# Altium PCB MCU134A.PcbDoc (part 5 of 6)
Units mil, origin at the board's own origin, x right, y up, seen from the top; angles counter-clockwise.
Board outline 4163.98 x 2693.8 mil, 6 copper layers (Top Layer, GND1, SIG1, PWR, GND2, Bottom), stack 58.132 mil thick; 218 components, 287 nets, 1260 pads, 770 vias.
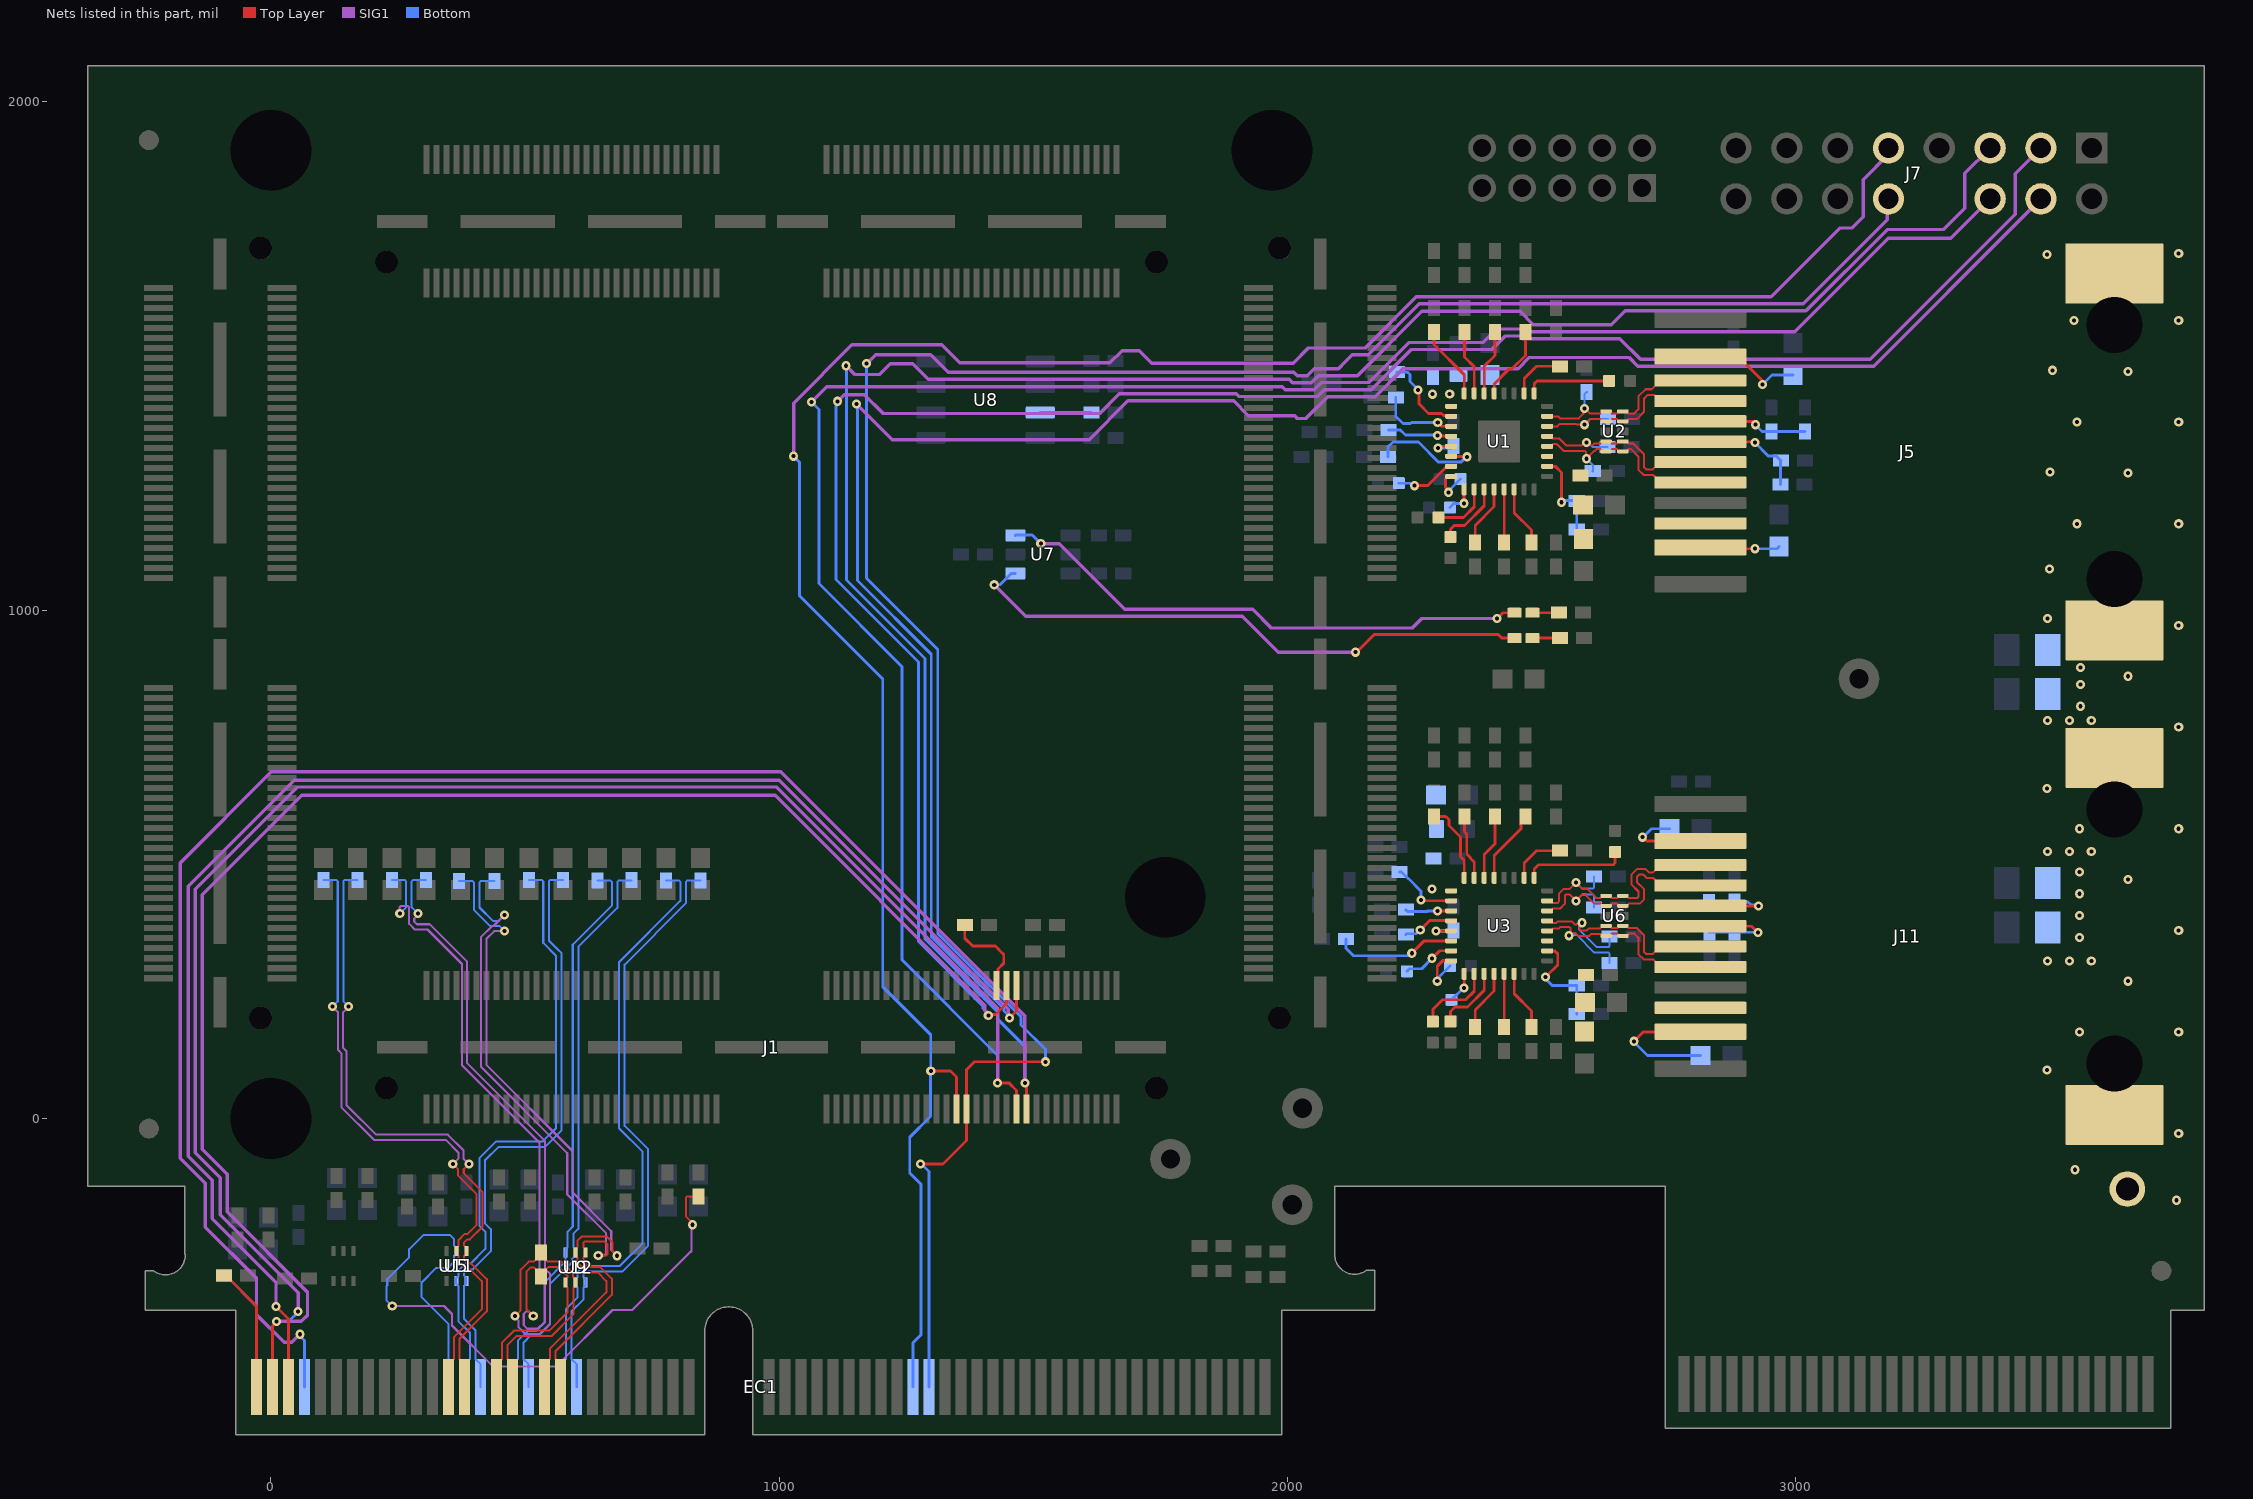
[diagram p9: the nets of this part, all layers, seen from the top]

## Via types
v1: diameter 18, hole 8, Top Layer to Bottom, tented both sides, 761 vias
v2: diameter 19.68, hole 7.87, Top Layer to Bottom, tented both sides, 9 vias

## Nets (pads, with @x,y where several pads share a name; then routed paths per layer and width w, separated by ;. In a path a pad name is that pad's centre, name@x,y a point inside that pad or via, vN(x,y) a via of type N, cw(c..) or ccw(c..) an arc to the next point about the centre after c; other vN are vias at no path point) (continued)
HSEC_PIN25: EC1.25 R103.1 U5.5 | length 1310
  Top Layer w4: EC1.25@349.86,-528.32 349.86,-484.03 360.11,-473.78 360.11,-430.36 415,-375.47 415,-320.36 390.24,-295.6 382.58,-295.6 369.34,-282.36 369.34,-270.66 367,-268.31 366.94,-268.31 365,-266.38 U5.5@365,-260.47 365,-254.57 366.94,-252.63 367,-252.63 369.34,-250.29 369.34,-239.31 381.65,-227 387.04,-227 405,-209.04 405,-148.98 368.5,-112.48 368.5,-99.9 358.6,-90 v1(358,-90)
  SIG1 w4.2: v1(121.07,220) 131.97,209.1 131.97,134.78 138.75,128 138.75,21.83 202.78,-42.2 344.1,-42.2 368.9,-67 368.9,-79.1 v1(358,-90)
  Bottom w4: R103.1@103.59,468.94 129.23,468.94 131.57,466.59 131.57,230.5 v1(121.07,220)
HSEC_PIN26: EC1.26 R114.1 U11.2 | length 1478.6
  Top Layer w4: v1(829.79,-209.28) 829.79,-206.24 816.38,-192.83 816.38,-156.25 818.72,-153.91 R114.1@841.45,-153.91
  SIG1 w4.2: v1(238.77,-369.17) 238.84,-369.1 340.8,-369.1 356.43,-384.73 356.43,-407.43 437.46,-488.46 560.77,-488.46 672.22,-377 711.23,-377 803.91,-284.32 804.02,-284.32 821.57,-266.76 ; 821.59,-266.76 827.6,-260.75 827.6,-211.46 v1(829.79,-209.28)
  Bottom w4: v1(238.77,-369.17) 227.19,-357.59 227.19,-330.59 229,-328.78 229,-316.44 272,-273.44 272,-257.44 300.44,-229 351.87,-229 360.66,-237.79 360.66,-250.29 363,-252.63 363.06,-252.63 365,-254.57 U11.2@365,-260.47 ; EC1.26@349.86,-528.32 349.86,-404.86 296.5,-351.5 296.5,-322.84 325.22,-294.12 348.61,-294.12 360.34,-282.39 360.34,-270.66 362.69,-268.31 362.75,-268.31 364.69,-266.38 U11.2@364.69,-260.47
HSEC_PIN27: EC1.27 R104.1 U5.4 | length 1308.3
  Top Layer w4: EC1.27@381.36,-528.32 381.36,-484.03 371.11,-473.78 371.11,-433.5 425,-379.62 425,-316.21 393.39,-284.6 387.14,-284.6 380.34,-277.8 380.34,-270.66 382.69,-268.31 382.75,-268.31 384.69,-266.38 U5.4@384.69,-260.47 384.69,-254.57 382.75,-252.63 382.69,-252.63 380.34,-250.29 380.34,-243.87 386.21,-238 391.6,-238 416,-213.6 416,-144.42 379.5,-107.92 379.5,-99.9 389.4,-90 v1(390,-90)
  SIG1 w4.2: v1(153.07,220) 142.17,209.1 142.17,139 145.96,135.21 148.95,132.22 148.95,26.05 207,-32 348.32,-32 379.1,-62.78 379.1,-79.1 v1(390,-90)
  Bottom w4: v1(153.07,220) 142.57,230.5 142.57,466.59 144.92,468.94 R104.1@170.55,468.94
HSEC_PIN28: EC1.28 R115.1 U11.5 | length 1201
  Bottom w4: EC1.28@381.36,-528.32 381.36,-484.03 391.61,-473.78 391.61,-421.61 388.39,-418.39 369.03,-399.03 369.03,-348.28 369.03,-329.71 366.68,-327.37 366.62,-327.37 364.69,-325.43 364.69,-313.62 366.62,-311.69 367,-311.69 369.34,-309.34 369.34,-298.84 382.33,-285.86 392.72,-285.86 422,-256.57 422,-222.65 410.15,-210.8 410.15,-78.29 443.44,-45 535,-45 561,-19 561,320.44 535.92,345.53 535.92,466.59 533.57,468.94 R115.1@507.7,468.94
HSEC_PIN30: EC1.30 R116.1 U11.4 | length 1200.6
  Bottom w4: EC1.30@412.86,-528.32 412.86,-484.03 402.61,-473.78 402.61,-417.05 399.39,-413.83 380.03,-394.47 380.03,-343.73 380.03,-329.71 382.37,-327.37 382.43,-327.37 384.37,-325.43 384.37,-313.31 382.75,-311.69 382.69,-311.69 380.34,-309.34 380.34,-303.4 386.88,-296.86 397.27,-296.86 433,-261.13 433,-218.1 421.15,-206.25 421.15,-82.85 448,-56 539.56,-56 572,-23.56 572,325 564,333 546.92,350.08 546.92,466.59 549.26,468.94 R116.1@575.14,468.94
HSEC_PIN31: C25.1 EC1.31 R105.1 U9.1 | length 1689
  Top Layer w4: EC1.31@444.35,-528.32 444.35,-484.03 454.41,-473.98 454.41,-441.45 478.41,-417.45 547.55,-417.45 584.01,-380.99 584.01,-332.85 581.66,-330.5 581.6,-330.5 579.66,-328.57 579.66,-316.76 583.52,-312.9 583.52,-309.16 566.9,-292.55 546,-292.55 C25.1@541.22,-297.33 ; v1(516.29,-388.69) 502.63,-375.02 502.63,-302.07 511.73,-292.97 517.22,-292.97 C25.1@531.41,-307.16 ; C25.1@531.41,-311.09 C25.1@531.41,-307.14 ; C25.1@541.22,-297.34 C25.1@531.42,-307.14
  SIG1 w4.2: v1(253.65,403) 253,403.65 253,415 256.14,418.14 268.73,418.14 271.97,414.9 271.97,382.98 283.15,371.8 308.1,371.8 376,303.9 376,104.49 528.89,-48.4 528.89,-299.77 538.9,-309.78 538.9,-399.87 524.77,-414 504.79,-414 497.62,-406.83 497.62,-384.8 502.64,-379.78 507.04,-379.78 515.94,-388.69 v1(516.29,-388.69)
  Bottom w4: R105.1@237.93,468.94 263.81,468.94 266.15,466.59 266.15,415.5 v1(253.65,403)
HSEC_PIN33: C25.2 EC1.33 R106.1 U9.2 | length 1690.6
  Top Layer w4: EC1.33@475.85,-528.32 475.85,-484.03 465.41,-473.59 465.41,-467.75 465.41,-446 482.96,-428.45 552.1,-428.45 595.01,-385.55 595.01,-332.85 597.35,-330.5 597.41,-330.5 599.35,-328.57 599.35,-316.76 594.52,-311.92 594.52,-304.61 571.46,-281.55 545.01,-281.55 541.22,-277.75 541.22,-277.6 531.57,-267.94 531.41,-267.94 C25.2@531.41,-263.85 ; v1(480.29,-388.69) 491.63,-377.35 491.63,-297.52 507.18,-281.97 517.22,-281.97 C25.2@531.41,-267.79
  SIG1 w4.2: v1(289.65,403) 289.65,400.54 282.17,393.06 282.17,387.2 287.38,382 312.32,382 386.2,308.12 386.2,108.72 539.09,-44.17 539.09,-295.55 549.1,-305.56 549.1,-404.1 529,-424.2 500.56,-424.2 487.42,-411.06 487.42,-398.05 480.29,-390.92 v1(480.29,-388.69)
  Bottom w4: v1(289.65,403) 277.15,415.5 277.15,466.59 279.49,468.94 R106.1@305.37,468.94
HSEC_PIN34: EC1.34 R117.1 U12.1 | length 1113.5
  Bottom w4: EC1.34@475.85,-528.32 475.85,-484.03 486.1,-473.78 486.1,-437.9 507,-417 523.51,-417 539,-401.51 539,-322 579.66,-281.34 579.66,-269.51 U12.1@579.66,-263.61 579.66,-257.7 U12.1@581.6,-255.76 ; U12.1@581.66,-255.76 584.01,-253.42 584.01,-222.65 594,-212.66 594,342 670.8,418.8 670.8,465.61 668.46,467.95 R117.1@642.58,467.95
HSEC_PIN36: EC1.36 R118.1 U12.2 | length 1117.1
  Bottom w4: EC1.36@507.34,-528.32 507.34,-484.03 497.1,-473.78 497.1,-441.05 511.14,-427 527.66,-427 549,-405.66 549,-326.14 592.6,-282.54 592.6,-276.26 599.35,-269.51 U12.2@599.35,-263.61 599.35,-257.7 U12.2@597.41,-255.76 ; U12.2@597.35,-255.76 595.01,-253.42 595.01,-227.21 605,-217.21 605,337.44 681.8,414.24 681.8,465.61 684.14,467.95 R118.1@710.02,467.95
HSEC_PIN37: EC1.37 R107.1 U9.5 | length 1417.9
  Top Layer w4: EC1.37@538.84,-528.32 538.84,-484.03 549.09,-473.78 549.09,-453.35 660,-342.44 660,-320.05 642.95,-303 623,-303 603.69,-283.69 603.69,-273.79 601.35,-271.45 601.29,-271.45 599.35,-269.51 U9.5@599.35,-263.61 599.35,-257.7 601.29,-255.76 601.35,-255.76 603.69,-253.42 603.69,-240.1 611.48,-232.31 660.76,-232.31 672,-243.55 672,-261.04 680.75,-269.79 v1(680.75,-270.19)
  SIG1 w4.2: v1(460,368.5) 439.5,368.5 424,353 424,105.42 593.49,-64.06 593.49,-145.55 669.79,-221.86 669.79,-258.83 v1@680.75,-269.79 ; v1(680.75,-270.19) v1@680.75,-269.79 ; v1@680.85,-269.89 v1@680.75,-269.79
  Bottom w4: R107.1@370,466.69 397.16,466.69 399.5,464.35 399.5,410.44 431.71,378.24 450.26,378.24 v1(460,368.5)
HSEC_PIN39: EC1.39 R108.1 U9.4 | length 1413.8
  Top Layer w4: EC1.39@570.34,-528.32 570.34,-484.03 560.09,-473.78 560.09,-457.91 671,-347 671,-315.5 648.32,-292.82 626.96,-292.82 614.69,-280.55 614.69,-273.79 617.03,-271.45 617.1,-271.45 619.03,-269.51 U9.4@619.03,-263.61 619.03,-257.7 617.1,-255.76 617.03,-255.76 614.69,-253.42 614.69,-244.65 617.03,-242.31 656.62,-242.31 661.9,-247.59 661.9,-267.42 659.32,-270 v1(644.19,-270)
  SIG1 w4.2: v1(460,400.5) 438.2,378.7 435.28,378.7 413.8,357.22 413.8,101.2 583.29,-68.29 583.29,-149.78 659.59,-226.08 659.59,-265.62 655.21,-270 v1(644.19,-270)
  Bottom w4: R108.1@440,466.69 412.84,466.69 410.5,464.35 410.5,415 437.26,388.24 447.16,388.24 459.42,400.5 v1(460,400.5)
HSEC_PIN40: EC1.40 R119.1 U12.5 | length 1204.3
  Bottom w4: EC1.40@570.34,-528.32 570.34,-484.03 580.59,-473.78 580.59,-375.27 603.69,-352.16 603.69,-332.85 601.35,-330.5 601.29,-330.5 599.35,-328.57 U12.5@599.35,-322.66 599.35,-316.76 601.29,-314.82 601.35,-314.82 603.69,-312.48 603.69,-302.26 615.47,-290.49 686.57,-290.49 731.36,-245.7 731.36,-65.36 685,-19 685,307.32 805.68,428 805.68,465.61 803.34,467.95 R119.1@777.46,467.95
HSEC_PIN42: EC1.42 R120.1 U12.4 | length 1204.3
  Bottom w4: EC1.42@601.83,-528.32 601.83,-484.03 591.59,-473.78 591.59,-379.82 614.69,-356.72 614.69,-332.85 617.03,-330.5 617.1,-330.5 619.03,-328.57 U12.4@619.03,-322.66 619.03,-316.76 617.1,-314.82 617.03,-314.82 614.69,-312.48 614.69,-306.82 620.02,-301.49 691.13,-301.49 742.36,-250.26 742.36,-60.8 696,-14.44 696,302.76 816.68,423.44 816.68,465.61 819.03,467.95 R120.1@844.9,467.95
MCU_SCI_RX: EC1.76 J1.33 J7.9 | length 4660.7
  Top Layer w5.66: v1(1298.5,93.41) 1337.51,93.41 1349.17,81.75 J1.33@1349.17,18.5
  SIG1 w6.66: v1(1028.49,1303) 1028.49,1407.18 1143.37,1522.06 1320.39,1522.06 1355.79,1486.66 1650.9,1486.66 1674.91,1510.66 1708.59,1510.66 1733.03,1486.22 2011.54,1486.22 2041.24,1515.93 2153.24,1515.93 2254,1616.68 2951.85,1616.68 3087.17,1752 3111,1752 3133,1774 3133,1847 3182.94,1896.94 J7.9@3182.94,1909.38
  Bottom w5.66: v1(1028.49,1303) 1040.24,1291.25 1040.24,1028.42 1204,864.66 1204,259 1298.5,164.5 v1(1298.5,93.41) 1298.02,92.92 1298.02,3.64 1257.17,-37.21 1257.17,-107.17 1279.5,-129.5 1279.5,-425.71 1263.66,-441.56 EC1.76@1263.66,-527.92
MCU_SCI_TX: EC1.78 J1.31 J7.10 | length 4579.4
  Top Layer w5.66: v1(1278,-90) 1322.31,-90 1368.86,-43.45 J1.31@1368.86,18.5 1368.86,95.91 1384.36,111.41 v1(1523.99,111.4)
  SIG1 w6.66: v1(1172,1485.18) 1189.82,1503 1298,1503 1333,1468.01 2012.99,1468.01 2019.57,1461.43 2039.09,1461.43 2052.98,1475.32 2100.74,1475.32 2114.24,1488.81 2114.24,1489.16 2127.34,1502.27 2158.9,1502.27 2259.66,1603.02 3014.97,1603.02 3180.43,1768.48 3180.43,1806.87 J7.10@3182.94,1809.38
  Bottom w5.66: v1(1172,1485.18) 1172,1063 1312.17,922.83 1312.17,363.69 1475.95,199.91 1475.95,184.05 1523.99,136.01 v1(1523.99,111.4) ; v1(1278,-90) 1280,-90 1294.75,-104.75 EC1.78@1294.75,-528.32
MCU_TCK: EC1.5 J1.22 J7.4 | length 6974.8
  Top Layer w5.66: v1(10,-370) 34.9,-394.9 EC1.5@34.9,-528.32 ; v1(1453.36,197.28) 1453.36,197.49 1467.28,211.41 J1.22@1467.28,261.5
  SIG1 w6.66: v1(10,-370) 10,-322 -115,-197 -115,-121.74 -162.32,-74.42 -162.32,457 46.34,665.66 1000.7,665.66 1451.19,215.17 1451.19,199.45 v1(1453.36,197.28) ; v1(1152,1405.83) 1222.26,1335.57 1610.18,1335.57 1686.47,1411.86 1894.31,1411.86 1923.56,1382.6 2014.31,1382.6 2019.76,1377.16 2036.31,1377.16 2079.5,1420.36 2173,1420.36 2227.64,1475 2454,1475 2476.33,1497.33 2672.35,1497.33 2689.34,1480.34 3153.9,1480.34 3445.66,1772.1 J7.4@3482.94,1809.38
  Bottom w5.66: v1(1152,1405.83) 1154,1403.83 1154,1058.7 1299.51,913.19 1299.51,358.45 1442.83,215.13 1442.83,211.16 1453.36,200.62 v1(1453.36,197.28)
MCU_TDI: EC1.8 J1.19 J7.5 | length 7385.2
  Top Layer w5.66: v1(1483.55,69.77) 1483.55,66.43 1486.97,63.02 J1.19@1486.97,18.5
  SIG1 w6.66: v1(57.25,-424.73) 41.25,-440.73 26.43,-440.73 -28.33,-385.97 -28.33,-314.67 -129.26,-213.74 -129.26,-127.92 -178.34,-78.84 -178.34,502.58 1.08,682 1003.68,682 1483.55,202.13 v1(1483.55,69.77) ; v1(1132,1481) 1149.33,1463.67 1197.36,1463.67 1218.69,1485 1263,1485 1293.65,1454.35 2003.65,1454.35 2010.23,1447.77 2047.46,1447.77 2061.35,1461.66 2137.61,1461.66 2137.8,1461.84 2138.77,1461.84 2264.92,1588 2458,1588 2484.26,1561.74 2637.37,1561.74 2665,1589.36 3020.63,1589.36 3180.27,1749 3290.97,1749 3333,1791.03 3333,1859.44 J7.5@3382.94,1909.38
  Bottom w5.66: v1(57.25,-424.73) 57.25,-428.07 66.4,-437.22 EC1.8@66.4,-528.32 ; v1(1132,1481) 1132.83,1480.17 1132.83,1059.18 1286.85,905.16 1286.85,353.2 1430.17,209.88 1430.17,195.26 1483.55,141.88 v1(1483.55,69.77)
MCU_TDO: EC1.6 J1.21 J7.6 | length 7125.2
  Top Layer w5.66: v1(1430,70) 1451.89,70 1467.28,54.61 J1.21@1467.28,18.5
  SIG1 w6.66: v1(53.21,-379.96) 54,-379.17 54,-343.08 -99.73,-189.35 -99.73,-116.56 -148.66,-67.63 -148.66,451.34 52,652 995.05,652 1430,217.05 v1(1430,70) ; v1(1064,1410) 1093.71,1439.71 1990.29,1439.71 1995.89,1434.11 2053.12,1434.11 2067.01,1448 2160,1448 2238.66,1526.66 2384.66,1526.66 2411.27,1553.27 2468.73,1553.27 2473.92,1548.08 2998.66,1548.08 3182.59,1732 3305.56,1732 J7.6@3382.94,1809.38
  Bottom w5.66: EC1.6@34.9,-528.32 34.9,-399.65 53.21,-381.35 v1(53.21,-379.96) ; v1(1064,1410) 1064,1409.23 1078.22,1395 1078.22,1052.4 1242.16,888.46 1242.16,311.65 1430,123.81 v1(1430,70)
MCU_TMS: EC1.3 J1.24 J7.3 | length 7034.6
  Top Layer w5.66: EC1.3@3.41,-528.32 3.41,-408.29 10.92,-400.78 v1(10.92,-399.29) ; v1(1411.67,202.5) 1413.54,204.37 1425.85,204.37 1447.6,226.12 J1.24@1447.6,261.5
  SIG1 w6.66: v1(10.92,-399.29) 59.8,-399.29 72.03,-387.06 72.03,-341.79 -86.07,-183.69 -86.07,-110.07 -135,-61.14 -135,440 60.58,635.58 992.15,635.58 1404.91,222.82 1404.91,212.33 1411.67,205.57 v1(1411.67,202.5) ; v1(1115,1411) 1128.16,1424.16 1167.39,1424.16 1204.54,1387 1630.59,1387 1669.11,1425.52 1899.96,1425.52 1905.04,1420.45 2058.78,1420.45 2072.35,1434.02 2165.34,1434.02 2244.32,1513 2402.69,1513 2429.31,1539.61 2458.39,1539.61 2463.58,1534.42 2654.58,1534.42 2695,1494 3146.71,1494 3432,1779.29 3432,1858.44 J7.3@3482.94,1909.38
  Bottom w5.66: v1(1115,1411) 1112.64,1408.64 1112.64,1402.15 1112,1401.51 1112,1060.5 1274.19,898.31 1274.19,347.96 1401.54,220.61 1401.54,215.97 1411.67,205.84 v1(1411.67,202.5)
NetC1_1: C1.1 C2.1 J5.5 | length 214.4
  Top Layer w5.66: J5.5@2812.8,1371.66 2914.34,1371.66 v1(2921,1365)
  Bottom w5.66: v1(2921,1365) 2934.24,1351.76 C2.1@2953,1351.76 C1.1@3019,1351.76
NetC3_1: C3.1 C8.1 U1.2 | length 179.6
  Top Layer w5.66: U1.2@2511.45,1283.11 2527.15,1283.11 2539.46,1270.79 v1(2539.49,1212.41)
  Bottom w5.66: v1(2539.49,1212.41) 2542.2,1212.41 2545.41,1215.62 2569.09,1215.62 C3.1@2569.54,1215.17 C8.1@2569.54,1158.65
NetC9_1: C9.1 C10.1 J5.6 | length 221.3
  Top Layer w5.66: J5.6@2812.8,1331.51 2918.49,1331.51 v1(2920,1330)
  Bottom w5.66: v1(2920,1330) 2946.39,1303.61 2962.09,1303.61 C9.1@2971.08,1294.63 2970.66,1294.21 C10.1@2970.66,1247
NetC11_1: C11.1 C13.1 R22.2 U1.3
NetC12_1: C12.1 C14.2 R21.1 U1.17
  other v1: 2286,1425 2319.54,1425.07
NetC15_1: C15.1 C16.1 R55.2 U3.3
NetC17_2: C17.2 C18.1 R54.1 U3.17
  other v1: 2284.99,451.67
NetC41_1: C41.1 C42.1 J11.5 | length 215.3
  Top Layer w5.66: J11.5@2812.8,418.38 2813.19,418 v1(2927,418)
  Bottom w5.66: C42.1@2829.4,426.1 2880,426.1 2906.68,426.1 2912.42,420.36 2924.64,420.36 v1(2927,418)
NetC47_1: C47.1 C48.1 U3.2 | length 205.8
  Top Layer w5.66: v1(2508,278) 2532.09,302.09 2532.09,323.95 2526.96,329.07 2512.2,329.07 U3.2@2511.45,329.83
  Bottom w5.66: v1(2508,278) 2508,274.66 2516.62,266.04 2516.62,265.89 2520.62,261.89 C48.1@2569.54,261.89 C47.1@2569.54,205.37
NetC49_1: C49.1 C50.1 J11.6 | length 214
  Top Layer w5.66: J11.6@2812.8,378.23 2913.49,378.23 2925.72,366 v1(2926,366)
  Bottom w5.66: C50.1@2830.36,366.22 C49.1@2880.36,366.22 2925.78,366.22 v1(2926,366)
NetD1_1: D1.1 R90.2 | length 51.8
  Top Layer w5.66: D1.1@2482.43,995 R90.2@2534.25,995
NetD1_2: D1.2 U7.6 | length 1070.8
  Top Layer w5.66: v1(2412.76,983.68) 2413.41,983.68 2424.73,995 D1.2@2447,995
  SIG1 w6.66: v1(1515,1130.96) 1551.04,1130.96 1680.32,1001.68 1931.66,1001.68 1968.34,965 2246,965 2264.68,983.68 v1(2412.76,983.68)
  Bottom w5.66: U7.6@1464.8,1147.21 1465.59,1148 1497.96,1148 v1(1515,1130.96)
NetD2_1: D2.1 R93.2 | length 53.8
  Top Layer w5.66: D2.1@2482.43,945 R93.2@2536.21,945
NetD2_2: D2.2 U7.4 | length 1146.4
  Top Layer w5.66: v1(2134,917.39) 2136.39,917.39 2171,952 2415,952 2422,945 D2.2@2447,945
  SIG1 w6.66: v1(1423.4,1050) 1485.38,988.02 1911.65,988.02 1982.28,917.39 v1(2134,917.39)
  Bottom w5.66: v1(1423.4,1050) 1434.52,1050 1456.93,1072.4 U7.4@1464.8,1072.4
NetEC1_1: EC1.1 R45.1 | length 247.8
  Top Layer w5.66: R45.1@-92.24,-309.39 -88.31,-309.39 -28.09,-369.61 EC1.1@-28.09,-528.32
NetEC1_2: EC1.2 R46.1 | length 247.8
  Bottom w5.66: R46.1@-92.24,-309.39 -88.31,-309.39 -28.09,-369.61 EC1.2@-28.09,-528.32
NetJ1_26: J1.26 R36.1 | length 183.4
  Top Layer w5.66: R36.1@1365.38,381 1365.38,354.62 1381,339 1426,339 1433,332 1433,331.52 1441.94,322.58 1441.94,305.36 1430.61,294.03 1430.61,264.2 J1.26@1427.91,261.5
NetJ5_2: J5.2 R38.2 | length 217.4
  Top Layer w5.66: J5.2@2812.8,1499.22 2887.41,1499.22 2935,1451.63 v1(2935,1444)
  Bottom w5.66: v1(2935,1444) 2954.01,1463.01 R38.2@2995,1463.01
NetJ5_11: J5.11 R25.2 | length 157.7
  Top Layer w5.66: J5.11@2812.8,1123.63 2815.44,1121 v1(2920,1121)
  Bottom w5.66: v1(2920,1121) 2963.76,1121 R25.2@2967.76,1125
NetJ11_2: J11.2 R87.2 | length 176.7
  Top Layer w5.66: v1(2698.99,553.33) 2699.93,553.33 2707.32,545.94 J11.2@2812.8,545.94
  Bottom w5.66: v1(2698.99,553.33) 2700.03,553.33 2716.72,570.02 R87.2@2751.93,570.02
NetJ11_11: J11.11 R79.2 | length 282.4
  Top Layer w5.66: v1(2682.02,151.75) 2700.63,170.35 J11.11@2812.8,170.35
  Bottom w5.66: v1(2682.02,151.75) 2682.02,150.05 2708.6,123.47 R79.2@2813.21,123.47
NetR2_2: R2.2 U1.21 | length 59.8
  Top Layer w5.66: v1(2296.37,1319.06) 2299.71,1319.06 2303.13,1322.48 U1.21@2322.47,1322.48
  Bottom w5.66: v1(2296.37,1319.06) 2322.96,1319.06 R2.2@2326.96,1323.05
NetR4_2: R4.2 U1.10 | length 109.4
  Top Layer w5.66: U1.10@2466.17,1426.81 2466.17,1456.14 2490.03,1480 R4.2@2536.38,1480
NetR5_1: R5.1 U1.23 | length 120.8
  Top Layer w5.66: v1(2250,1245) 2275.79,1245 2311.8,1281.02 2320.38,1281.02 U1.23@2322.47,1283.11
  Bottom w5.66: R5.1@2219.45,1249.88 2241.78,1249.88 2246.66,1245 v1(2250,1245)
NetR9_2: R9.2 U1.19 | length 156
  Top Layer w5.66: v1(2296.05,1369.05) 2296.63,1369.05 2303.83,1361.85 U1.19@2322.47,1361.85
  Bottom w5.66: R9.2@2213.41,1418.51 2213.41,1381.38 2227.61,1367.17 2242.39,1367.17 2244.42,1369.2 2295.9,1369.2 v1(2296.05,1369.05)
NetR10_1: R10.1 U1.27 | length 133.5
  Top Layer w5.66: R10.1@2320.94,1143.74 2320.94,1159.11 2328.52,1166.69 2348.77,1166.69 2387.43,1205.35 U1.27@2387.43,1237.83
NetR11_1: R11.1 U1.26 | length 112.9
  Top Layer w5.66: R11.1@2297.83,1182.57 2346.75,1182.57 2367.75,1203.57 U1.26@2367.75,1237.83
NetR12_1: R12.1 U1.25 | length 58.8
  Top Layer w5.66: v1(2347.78,1210.31) 2347.92,1210.45 2347.92,1237.69 U1.25@2348.06,1237.83
  Bottom w5.66: R12.1@2320.02,1202.13 2327.6,1209.71 2347.18,1209.71 v1(2347.78,1210.31)
NetR13_2: R13.2 U1.18 | length 166.3
  Top Layer w5.66: v1(2257.13,1433.03) 2259.49,1430.67 2259.49,1405.51 2277.75,1387.25 2303.43,1387.25 2307.68,1383.01 2321,1383.01 U1.18@2322.47,1381.53
  Bottom w5.66: R13.2@2215.47,1468.23 2236.77,1468.23 2241.16,1463.84 2241.16,1450.01 2257.13,1434.04 v1(2257.13,1433.03)
NetR14_1: R14.1 U1.24 | length 78.3
  Top Layer w5.66: v1(2317.12,1231.99) 2317.12,1235.23 2311.24,1241.12 2311.24,1259.08 2315.58,1263.42 U1.24@2322.47,1263.42
  Bottom w5.66: v1(2317.12,1231.99) 2317.12,1234.35 R14.1@2340.75,1257.97
NetR15_2: R15.2 U1.15 | length 128.8
  Top Layer w5.66: R15.2@2348.47,1547.63 2348.47,1498.48 2367.75,1479.2 U1.15@2367.75,1426.81
NetR16_2: R16.2 U1.14 | length 129.5
  Top Layer w5.66: U1.14@2387.43,1426.81 2387.43,1480.28 2408.47,1501.32 R16.2@2408.47,1547.63
NetR17_2: R17.2 U1.13 | length 149.3
  Top Layer w5.66: U1.13@2407.12,1426.81 2407.12,1445.29 2436.83,1475 2442.2,1475 2468.6,1501.4 R17.2@2468.6,1547.5
NetR18_2: R18.2 U1.20 | length 128.6
  Top Layer w5.66: v1(2295.83,1344.05) 2296.78,1343.11 2321.53,1343.11 U1.20@2322.47,1342.16
  Bottom w5.66: R18.2@2199.03,1354.64 2222.24,1354.64 2232.46,1344.42 2295.46,1344.42 v1(2295.83,1344.05)
NetR19_1: R19.1 U1.30 | length 118.7
  Top Layer w5.66: U1.30@2446.49,1237.83 2446.49,1191.54 2480.52,1157.51 R19.1@2480.52,1133.25
NetR20_2: R20.2 U1.22 | length 232.4
  Top Layer w5.66: U1.22@2322.14,1302.07 2322.36,1302.29 2353.43,1302.29 v1(2353.93,1301.79)
  Bottom w5.66: R20.2@2197.8,1301.83 2197.8,1320.88 2208.1,1331.18 2257.85,1331.18 2297.76,1291.27 2341.43,1291.27 2351.95,1301.79 v1(2353.93,1301.79)
NetR23_2: R23.2 U1.9 | length 168.6
  Top Layer w5.66: U1.9@2485.86,1426.81 2485.86,1445.64 2491.34,1451.12 R23.2@2633.39,1451.12
NetR24_2: R24.2 U1.16 | length 145.5
  Top Layer w5.66: R24.2@2288.47,1547.63 2288.47,1523.01 2348.06,1463.42 U1.16@2348.06,1426.81
NetR26_2: R26.2 U1.28 | length 119.8
  Top Layer w5.66: R26.2@2369.79,1133.25 2369.79,1166.6 2406.94,1203.75 U1.28@2406.94,1237.66
NetR27_2: R27.2 U1.29 | length 104.6
  Top Layer w5.66: R27.2@2426.8,1133.25 U1.29@2426.8,1237.83
NetR32_2: R32.2 U3.9 | length 203.2
  Top Layer w5.66: U3.9@2485.86,473.53 2485.86,490.86 2494,499 2641.68,499 2645,502.32 R32.2@2645,524.33
NetR57_2: R57.2 U3.21 | length 64.5
  Top Layer w5.66: v1(2292.75,368.82) 2292.93,369.01 2322.29,369.01 U3.21@2322.47,369.2
  Bottom w5.66: v1(2292.75,368.82) 2326,368.82 R57.2@2326.96,369.77
NetR59_2: R59.2 U3.10 | length 109.4
  Top Layer w5.66: U3.10@2466.17,473.53 2466.17,502.86 2490.03,526.72 R59.2@2536.38,526.72
NetR60_1: R60.1 U3.23 | length 103.4
  Top Layer w5.66: v1(2285,315) 2299.83,329.83 U3.23@2322.47,329.83
  Bottom w5.66: R60.1@2235.71,289.55 2240.54,294.38 2264.38,294.38 v1(2285,315)
NetR64_2: R64.2 U3.19 | length 91.2
  Top Layer w5.66: v1(2295.78,408.14) 2296,408.35 2322.26,408.35 U3.19@2322.47,408.57
  Bottom w5.66: R64.2@2233.15,410.68 2236.47,407.35 2275.46,407.35 2276.25,408.14 v1(2295.78,408.14)
NetR65_1: R65.1 U3.27 | length 136.3
  Top Layer w5.66: R65.1@2320.94,190.46 2320.94,210.6 2329.82,219.49 2354.85,219.49 2387.43,252.07 U3.27@2387.43,284.55
NetR66_1: R66.1 U3.26 | length 154.5
  Top Layer w5.66: R66.1@2286.32,190.38 2286.32,214.25 2305.52,233.44 2350.91,233.44 2367.75,250.29 U3.26@2367.75,284.55
NetR67_1: R67.1 U3.25 | length 62.1
  Top Layer w5.66: v1(2347.55,256.72) 2348.06,257.23 U3.25@2348.06,284.55
  Bottom w5.66: R67.1@2323.1,233.43 2346.39,256.72 v1(2347.55,256.72)
NetR68_2: R68.2 U3.18 | length 135.6
  Top Layer w5.66: v1(2263.02,430.01) 2264.78,428.25 U3.18@2322.47,428.25
  Bottom w5.66: R68.2@2220.48,485.04 2224.42,485.04 2237.62,471.83 2238.39,471.83 2262.72,447.5 2262.72,430.31 v1(2263.02,430.01)
NetR69_1: R69.1 U3.24 | length 101.9
  Top Layer w5.66: v1(2295,270) 2295,299.4 2305.97,310.37 2322.24,310.37 U3.24@2322.47,310.14
  Bottom w5.66: v1(2295,270) 2297.36,272.36 2297.36,277.36 R69.1@2320,300
NetR70_2: R70.2 U3.15 | length 128.8
  Top Layer w5.66: R70.2@2348.47,594.35 2348.47,564 2353.2,559.27 2353.2,520.26 2360.72,512.73 2360.72,511.73 2367.75,504.71 U3.15@2367.75,473.53
NetR71_2: R71.2 U3.14 | length 129.5
  Top Layer w5.66: U3.14@2387.43,473.53 2387.43,519.43 2408.47,540.47 R71.2@2408.47,594.35
NetR72_2: R72.2 U3.13 | length 146.2
  Top Layer w5.66: U3.13@2407.12,473.53 2407.12,517.33 2459.49,569.7 2459.49,585.37 R72.2@2468.47,594.35
NetR73_2: R73.2 U3.20 | length 100.8
  Top Layer w5.66: v1(2261.62,370.48) 2280.29,389.16 2322.2,389.16 U3.20@2322.47,388.88
  Bottom w5.66: R73.2@2233.15,361.72 2234.67,363.24 2253.09,363.24 2260.33,370.48 v1(2261.62,370.48)
NetR74_2: R74.2 U3.22 | length 241.1
  Top Layer w5.66: v1(2245,325) 2269.44,349.44 U3.22@2320.13,349.44
  Bottom w5.66: R74.2@2115.85,352.87 2115.85,334.15 2130,320 2236.66,320 2241.66,325 v1(2245,325)
NetR78_2: R78.2 U3.16 | length 159.1
  Top Layer w5.66: R78.2@2288.47,594.35 2311.65,594.35 2318,588 2318,576.57 2340.54,554.03 2340.54,515.02 2348.06,507.49 U3.16@2348.06,473.53
NetR80_2: R80.2 U3.28 | length 119.8
  Top Layer w5.66: R80.2@2369.79,179.97 2369.79,213.32 2406.94,250.47 U3.28@2406.94,284.38
NetR81_2: R81.2 U3.29 | length 104.6
  Top Layer w5.66: R81.2@2426.8,179.97 U3.29@2426.8,284.55
NetR82_2: R82.2 U3.30 | length 118.7
  Top Layer w5.66: U3.30@2446.49,284.55 2446.49,245.35 2480.52,211.31 R82.2@2480.52,179.97
NetR96_1: R96.1 U8.7 | length 101.1
  Bottom w5.66: U8.7@1513.88,1389.03 R96.1@1614.97,1389.03
PHY0_RD_N: C45.2 J11.8 U3.4 U6.5 U6.6 | length 495.2
  Top Layer w4: U3.4@2511.45,369.2 2518.34,369.2 2522.68,373.54 2533.82,373.54 2536.82,376.54 2555.22,376.54 2557.57,374.2 2557.57,370.89 2557.22,370.55 2557.22,362.22 v1(2554.54,359.54) 2558.33,359.54 2563.35,364.57 2567.2,364.57 2572.77,359 2593.78,359 2597.48,362.7 2616.76,362.7 2618.99,360.47 U6.5@2619.05,360.47 ; U6.5@2620.11,359.35 U6.5@2627.29,359.35 2634.48,359.35 2636.41,361.29 2636.41,361.35 2638.76,363.7 2648.7,363.7 2651.04,361.35 2651.04,361.29 2652.98,359.35 2667.35,359.35 2669.29,361.29 2669.29,361.35 2671.63,363.7 2682.72,363.7 2690.92,355.5 2690.92,343.94 2690.92,326.85 2690.92,323.26 2701.39,312.79 2720.22,312.79 2734.26,298.75 J11.8@2812.8,298.75
  Bottom w4: v1(2554.54,359.54) 2556.03,361.03 2569.28,361.03 2604.16,326.15 2632.03,326.15 2634.38,323.81 C45.2@2634.38,305.8
PHY0_RD_P: C46.2 J11.7 U3.5 U6.4 U6.7 | length 493.9
  Top Layer w4: U3.5@2511.45,388.88 2518.34,388.88 2522.68,384.54 2529.26,384.54 2532.27,387.54 2559.78,387.54 2565.34,381.98 2568.66,381.98 2569,382.32 2577.32,382.32 v1(2580,385) 2580,381.21 2574.98,376.19 2574.98,372.34 2577.32,370 2589.23,370 2592.92,373.7 2614.83,373.7 2618.17,377.04 2618.17,377.1 2620.11,379.04 U6.4@2627.29,379.04 2634.48,379.04 2636.41,377.1 2636.41,377.04 2638.76,374.7 2648.7,374.7 2651.04,377.04 2651.04,377.1 2652.98,379.04 2667.35,379.04 2671.69,374.7 2687.27,374.7 2701.92,360.05 2701.92,343.94 2701.92,327.82 2702.88,326.85 2705.94,323.79 2719.15,323.79 2734.26,338.91 J11.7@2812.8,338.91
  Bottom w4: v1(2580,385) 2580,382.14 2573.52,375.66 2573.52,372.34 2608.71,337.15 2632.03,337.15 2634.38,339.5 C46.2@2634.38,357.5
PHY0_TD_N: C43.2 J11.4 U3.6 U6.2 U6.9 | length 492.9
  Top Layer w4: U3.6@2511.45,408.57 2518.34,408.57 2522.68,412.91 2536.56,412.91 2546,422.35 2546,438.16 2548.34,440.5 2555.5,440.5 v1(2568,428) 2580.5,440.5 2586,440.5 2589.86,436.64 2589.86,436.53 2603.64,422.75 2615.83,422.75 2618.17,420.41 2618.17,420.35 2620.11,418.41 U6.2@2627.29,418.41 2634.48,418.41 2636.41,420.35 2636.41,420.41 2638.76,422.75 2648.7,422.75 2651.04,420.41 2651.04,420.35 2652.98,418.41 2667.35,418.41 2671.69,422.75 2693.72,422.75 2702,431.03 2702,451 2688.06,464.94 2688.06,475.24 2692.81,480 2700.09,480 2706.8,473.29 2719.51,473.29 2734.26,458.54 J11.4@2812.8,458.54
  Bottom w4: v1(2568,428) 2581,441 2601.41,441 2603.76,438.66 C43.2@2603.76,415
PHY0_TD_P: C44.2 J11.3 U3.7 U6.1 U6.10 | length 490.1
  Top Layer w4: U3.7@2511.45,428.25 2518.34,428.25 2522.68,423.91 2532,423.91 2535,426.91 2535,442.71 2543.79,451.5 2555.5,451.5 v1(2568,464) 2580.5,451.5 2590.56,451.5 2601.93,440.12 2601.93,440.02 2608.2,433.75 2615.83,433.75 2618.17,436.09 2618.17,436.16 2620.11,438.09 U6.1@2627.29,438.09 2634.48,438.09 2636.41,436.16 2636.41,436.09 2638.76,433.75 2648.7,433.75 2651.04,436.09 2651.04,436.16 2652.98,438.09 2667.35,438.09 2669.29,436.16 2669.29,436.09 2671.63,433.75 2688.66,433.75 2691,436.09 2691,446.44 2677.06,460.39 2677.06,479.8 2688.26,491 2704.65,491 2711.36,484.29 2719.85,484.29 2734.26,498.7 J11.3@2812.8,498.7
  Bottom w4: v1(2568,464) 2580,452 2601.41,452 2603.76,454.34 C44.2@2603.76,476
PHY1_RD_N: C6.2 J5.8 U1.4 U2.5 U2.6 | length 409.8
  Top Layer w4: U1.4@2511.45,1322.48 2518.34,1322.48 2522.68,1326.82 2530.68,1326.82 2544.5,1313 2585.82,1313 2588.17,1310.66 2588.17,1298.56 v1(2588.72,1298) 2604.22,1313.5 2605.27,1313.5 2608.75,1316.98 2615.83,1316.98 2618.17,1314.63 2618.17,1314.57 2620.11,1312.63 U2.5@2627.29,1312.63 2634.48,1312.63 2636.41,1314.57 2636.41,1314.63 2638.76,1316.98 2648.7,1316.98 2651.04,1314.63 2651.04,1314.57 2652.98,1312.63 2667.35,1312.63 2671.69,1316.98 2676.38,1316.98 2690.92,1302.44 2690.92,1276.54 2701.39,1266.07 2720.22,1266.07 2734.26,1252.03 J5.8@2812.8,1252.03
  Bottom w4: v1(2588.72,1298) 2601.94,1284.78 2601.94,1274.35 C6.2@2601.02,1273.43
PHY1_RD_P: C7.2 J5.7 U1.5 U2.4 U2.7 | length 409.7
  Top Layer w4: U1.5@2511.45,1342.16 2518.34,1342.16 2522.68,1337.82 2535.24,1337.82 2549.06,1324 2579.38,1324 2585.38,1330 v1(2588.72,1330) 2591.9,1330 2597.4,1324.5 2600.71,1324.5 2604.19,1327.98 2615.83,1327.98 2618.17,1330.32 2618.17,1330.38 2620.11,1332.32 U2.4@2627.29,1332.32 2634.48,1332.32 2636.41,1330.38 2636.41,1330.32 2638.76,1327.98 2648.7,1327.98 2651.04,1330.32 2651.04,1330.38 2652.98,1332.32 2667.35,1332.32 2671.69,1327.98 2680.94,1327.98 2701.92,1307 2701.92,1281.1 2705.94,1277.07 2719.15,1277.07 2734.26,1292.19 J5.7@2812.8,1292.19
  Bottom w4: v1(2588.72,1330) 2591.6,1330 2600.77,1320.83 C7.2@2629.72,1320.83
PHY1_TD_N: C4.2 J5.4 U1.6 U2.2 U2.9 | length 406
  Top Layer w4: U1.6@2511.45,1361.85 2531.38,1361.85 2536.2,1366.66 2567.82,1366.66 2569.48,1365 v1(2585,1365) 2595.85,1375.85 2615.95,1375.85 2620.11,1371.69 2634.48,1371.69 2636.41,1373.63 2636.41,1373.69 2638.76,1376.03 2648.7,1376.03 2651.04,1373.69 2651.04,1373.63 2652.98,1371.69 U2.9@2660.16,1371.69 2667.35,1371.69 2669.29,1373.63 2669.29,1373.69 2671.63,1376.03 2687.27,1376.03 2701.92,1390.68 2701.92,1416.07 2709.63,1423.78 2722.3,1423.78 2734.26,1411.82 J5.4@2812.8,1411.82
  Bottom w4: v1(2585,1365) 2596.25,1376.25 C4.2@2630.96,1376.25
PHY1_TD_P: C5.2 J5.3 U1.7 U2.1 U2.10 | length 405.1
  Top Layer w4: U1.7@2511.45,1381.53 2532.71,1381.53 2536.58,1377.66 2573.62,1377.66 2582.32,1386.36 2582.32,1394.32 v1(2585,1397) 2586.28,1397 2596.43,1386.85 2615.58,1386.85 2620.11,1391.37 2634.48,1391.37 2636.41,1389.44 2636.41,1389.38 2638.76,1387.03 2648.7,1387.03 2651.04,1389.38 2651.04,1389.44 2652.98,1391.37 U2.10@2660.16,1391.37 2667.35,1391.37 2669.29,1389.44 2669.29,1389.38 2671.63,1387.03 2682.72,1387.03 2690.92,1395.23 2690.92,1420.62 2705.08,1434.78 2717.06,1434.78 2734.26,1451.98 J5.3@2812.8,1451.98
  Bottom w4: v1(2585,1397) 2585,1425.85 C5.2@2588.93,1429.78 C5.2@2590.16,1428.54
SHLD_GND: C19.1 C59.1 J5.10 J5.13 J5.14 J11.10 J11.13 J11.14 pad.6 R34.2 R89.2
  other v1: 3750,-161 3550,-101 3754,-30 3495,95 3559,170 3754,170 3654,270 3496,310 3539,310 3582,310 3559,356 3754,370 3559,399 3559,442 3654,470 3559,485 3496,525 3539,525 3582,525 3559,570 3754,570 3495,649 3754,770 3496,783 3539,783 3582,783 3561,811 3561,854 3654,870 3561,887 3754,970 3496,984 3500,1081 3554,1170 3754,1170 3654,1270 3501,1272 3554,1370 3754,1370 3654,1470 3506,1472 3548,1570 3754,1570 3495,1700 3754,1702
pads on no net: EC1.4 EC1.32 EC1.41 EC1.44 EC1.66 EC1.115 EC1.116 EC1.118 EC2.136 EC2.176 FID1.1 FID2.1 FID3.1 FID4.1 FID5.1 FID6.1 J1.47 J1.79 J1.80 J1.81 J1.82 J1.83 J1.84 J1.86 J1.88 J1.89 J1.90 J1.91 J1.92 J1.93 J1.94 J1.95 J1.96 J1.MH1 J1.MH2 J2.1 J2.2 J2.3 J2.4 J2.5 J2.6 J2.7 J2.8 J2.9 J2.10 J2.11 J2.12 J2.13 J2.14 J2.15 J2.16 J2.17 J2.18 J2.19 J2.20 J2.22 J2.24 J2.37 J2.39 J2.41 J2.42 J2.43 J2.44 J2.61 J2.62 J2.63 J2.64 J2.65 J2.66 J2.67 J2.68 J2.69 J2.70 J2.71 J2.72 J2.73 J2.74 J2.75 J2.76 J2.77 J2.78 J2.79 J2.80 J2.81 J2.82 J2.83 J2.84 J2.85 J2.86 J2.87 J2.88 J2.89 J2.90 J2.91 J2.92 J2.93 J2.94 J2.95 J2.96 J2.97 J2.98 J2.99 J2.100 J2.101 J2.102 J2.103 J2.104 J2.105 J2.106 J2.107 J2.108 J2.109 J2.110 J2.111 J2.112 J2.113 J2.114 J2.115 J2.116 J2.117 J2.118 J2.119 J2.120 J2.MH1 J2.MH2 J3.1 J3.3 J3.5 J3.7 J3.9 J3.11 J3.13 J3.15 J3.17 J3.19 J3.21 J3.23 J3.25 J3.32 J3.34 J3.36 J3.38 J3.40 J3.41 J3.42 J3.43 J3.44 J3.45 J3.46 J3.47 J3.48 J3.49 J3.50 J3.51 J3.52 J3.53 J3.54 J3.55 J3.56 J3.58 J3.60 J3.61 J3.62 J3.63 J3.64 J3.65 J3.66 J3.67 J3.68 J3.69 J3.70 J3.71 J3.72 J3.73 J3.74 J3.75 J3.77 J3.79 J3.81 J3.86 J3.98 J3.110 J3.MH1 J3.MH2 J4.1 J4.2 J4.3 J4.4 J4.5 J4.6 J4.7 J4.8 J4.9 J4.10 J4.11 J4.12 J4.13 J4.14 J4.15 J4.16 J4.17 J4.18 J4.19 J4.20 J4.21 J4.22 J4.23 J4.24 J4.25 J4.26 J4.27 J4.28 J4.29 J4.30 J4.31 J4.32 J4.33 J4.34 J4.35 J4.36 J4.37 J4.38 J4.39 J4.40 J4.41 J4.42 J4.43 J4.44 J4.45 J4.46 J4.47 J4.48 J4.49 J4.50 J4.51 J4.52 J4.53 J4.54 J4.55 J4.56 J4.57 J4.58 J4.59 J4.60 J4.61 J4.62 J4.63 J4.64 J4.65 J4.66 J4.67 J4.68 J4.69 J4.70 J4.71 J4.72 J4.73 J4.74 J4.75 J4.76 J4.77 J4.78 J4.79 J4.80 J4.81 J4.82 J4.83 J4.84 J4.85 J4.86 J4.87 J4.88 J4.89 J4.90 J4.91 J4.92 J4.93 J4.94 J4.95 J4.96 J4.97 J4.98 J4.99 J4.100 J4.101 J4.102 J4.103 J4.104 J4.105 J4.106 J4.107 J4.108 J4.109 J4.110 J4.111 J4.112 J4.113 J4.114 J4.115 J4.116 J4.117 J4.118 J4.119 J4.120 J4.MH1 J4.MH2 J5.9 J5.ALIGN1 J5.ALIGN2 J8.9 J11.9 J11.ALIGN1 J11.ALIGN2 MH1.1 MH2.1 MH3.1 MH4.1 U1.1 U1.8 U2.3@2627.29,1352 U2.8@2660.16,1352 U3.1 U3.8 U6.3@2627.29,398.72 U6.8@2660.16,398.72

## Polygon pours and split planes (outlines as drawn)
GND on Top Layer "Top Layer-GND" (solid, remove dead copper, pour order 132): 853.8,-555.16 853.8,-372.2 872.03,-353.97 929.97,-353.97 948.29,-372.29 948.29,-555.16 1989.23,-555.16 1989.23,-377.97 2171.95,-377.97 2171.95,-298.97 2155.96,-298.97 2146.2,-308.73 2119.1,-308.73 2092.95,-282.58 2092.95,-133.97 2743.26,-133.97 2743.26,-555.16 3738.54,-555.16 3738.54,-377.87 3803.95,-377.87 3803.95,2070.99 3803.94,2070.98 -360.03,2070.98 -360.02,2070.97 -360.02,-133.97 -169.05,-133.97 -168.55,-134.47 -168.55,-283.07 -191.19,-305.72 -225.3,-305.72 -231.05,-299.97 -247.05,-299.97 -247.05,-377.97 -70.05,-377.97 -70.05,-555.16 691.31,-555.16
3V3_OUT on Top Layer "NONET_L08_P-001" (solid, remove dead copper, pour order 34): 1423.27,295.13 1423.27,295.29 1431,303.02 1431,318.82 1417.4,332.42 1399.66,332.42 1391.7,324.46 1391.7,301.19 1402.22,290.67 1402.22,232.19 1414.23,232.19 1414.23,291.07 1418.3,295.13
SHLD_GND on Top Layer "NONET_L08_P-001" (solid, remove dead copper, pour order 1): 3604,-188 3778,-188 3778,1725 3766.97,1736.03 3489.97,1736.03 3475.97,1722.03 3475.97,1241.41 3444.56,1210 2928.55,1210 2901.43,1182.89 2742.79,1182.89 2742.79,1159.1 2743.02,1158.87 2901.43,1158.87 2910.3,1150 3457.94,1150 3475.97,1131.97 3475.97,255 2926.83,255 2901.43,229.6 2752.48,229.6 2752.48,205.59 2904.41,205.59 2925,185 3475.97,185 3475.97,78.17 3524.01,30.12 3524.01,-108.01
3V3_OUT on Top Layer "NONET_L08_P-001" (solid, remove dead copper, pour order 137): 575.12,-240.04 583.6,-248.52 583.6,-273.45 576.24,-280.81 520.25,-280.81 520.25,-249.31 536.33,-249.31 545.61,-240.04
3V3_OUT on Top Layer "NONET_L08_P-001" (solid, remove dead copper, pour order 37): 1957.02,-250 1977.77,-229.25 2015.75,-229.25 2045,-200 2045,-155 2030,-140 1987.33,-140 1932.33,-195 1915,-195 1906.74,-203.26 1906.74,-251.74 1906.74,-386.74 1945.34,-425.34 1945.34,-583.44 1966.99,-583.44 1966.99,-377.25 1954.33,-364.59 1954.33,-324.65 1957.02,-321.96
NetC15_1 on Top Layer "NONET_L08_P-001" (solid, remove dead copper, pour order 62): 2541,188.31 2541,327 2523.41,344.59 2500.79,344.59 2499.64,345.74 2499.64,353.28 2500.75,354.39 2501.21,354.39 2501.61,354.43 2562.48,354.43 2580.43,336.48 2601.45,315.46 2601.45,208.23 2601.94,207.73 2601.94,167.54 2601.46,167.06 2562.25,167.06
NetC17_2 on Top Layer "NONET_L08_P-001" (solid, remove dead copper, pour order 65): 2319.54,459.97 2326.66,452.86 2333.13,452.86 2334.73,451.26 2334.73,444.62 2333.13,443.01 2280.78,443.01 2273.66,450.13 2273.66,476.05 2281.21,483.6 2319.54,483.6
3V3_OUT on Top Layer "NONET_L-01_P-001" (solid, remove dead copper, pour order 116): 2443.19,883.7 2394.93,883.7 2388.84,889.78 2367.16,889.78 2358,880.63 2358,838.37 2369.03,827.34 2405.77,827.34 2424.73,846.3 2443.19,846.3
3V3_OUT on Top Layer "NONET_L-01_P-001" (solid, remove dead copper, pour order 94): 360,-220 385,-220 390,-215 390,-205 380,-195 359.17,-195 340,-214.17 340,-249.47 341.15,-250.4 341.38,-250.63 341.38,-270.31 349.25,-270.31 349.25,-230.75
3V3_OUT on Top Layer "NONET_L08_P-001" (solid, remove dead copper, pour order 90): 302.59,-297.59 327.3,-322.3 327.3,-342.7 315,-355 266.34,-355 256.02,-344.68 256.02,-297.79
3V3_OUT on Top Layer "NONET_L-01_P-001" (solid, remove dead copper, pour order 88): 112.2,-271.19 111,-270 75,-270 68.04,-263.04 68.04,-226.96 70,-225 90,-225 100,-235 125,-235 127.52,-237.52 127.52,-271.19
3V3_OUT on Top Layer "NONET_L08_P-001" (solid, remove dead copper, pour order 79): 95.75,-303.19 51.02,-303.19 51.02,-339.68 66.34,-355 100,-355 112.52,-342.48 112.52,-332.52 100.44,-320.44 100.44,-307.88
GND on Top Layer "NONET_L08_P-001" (solid, remove dead copper, pour order 86): 1971.29,-250.12 2024.71,-250.12 2033.91,-259.33 2033.91,-319.33 2028.91,-324.33 1971.65,-324.33 1971.29,-323.97 1971.29,-300.35
5V0_IN on Top Layer "NONET_L08_P-001" (solid, remove dead copper, pour order 18): 1437.46,392.46 1437.1,392.81 1396.87,392.81 1396.87,369.19 1416.09,349.97 1430,349.97 1459.97,320 1459.97,317.36 1480.96,296.36 1480.96,232.19 1512.66,232.19 1512.66,297.02 1520.78,305.15 1520.78,392.46
GND on Top Layer "NONET_L08_P-001" (solid, remove dead copper, pour order 85): 1536.53,317.05 1568.03,317.05 1577.87,307.21 1587.21,307.21 1595,315 1595,410 1585,420 1545,420 1536.53,411.53
GND on Top Layer "NONET_L08_P-001" (solid, remove dead copper, pour order 9): 2609.69,1276.35 2609.69,1252.72 2623.87,1238.55 2623.87,1188.54 2680.48,1188.54 2689.69,1197.75 2689.69,1244.53 2657.88,1276.35 2641.19,1276.35
NetC12_1 on Top Layer "NONET_L08_P-001" (solid, remove dead copper, pour order 6): 2326.66,1412.61 2334.73,1404.54 2334.73,1397.9 2333.13,1396.3 2292.64,1396.3 2273.66,1415.27 2273.66,1429.33 2281.21,1436.88 2326.66,1436.88
3V3_ETH on Top Layer "NONET_L08_P-001" (solid, remove dead copper, pour order 64): 2562.24,143.46 2627.64,143.46 2638.37,132.72 2638.37,101.45 2625.26,88.34 2577.99,88.34 2562.24,104.09
GND on Top Layer "NONET_L08_P-001" (solid, remove dead copper, pour order 63): 2616.04,323.06 2616.04,288.19 2623.87,280.35 2623.87,227.66 2672.89,227.66 2689.69,244.47 2689.69,291.25 2657.88,323.06 2641.19,323.06
3V3_ETH on Top Layer "NONET_L08_P-001" (solid, remove dead copper, pour order 0): 2564.15,1097.65 2667.59,1097.65 2667,1059 2650.53,1042.53 2579.89,1042.53 2564.15,1058.28
NetC11_1 on Top Layer "NONET_L08_P-001" (solid, remove dead copper, pour order 8): 2559.24,1123.35 2559.24,1266.76 2528.13,1297.87 2500.79,1297.87 2499.64,1299.02 2499.64,1306.56 2500.75,1307.67 2501.21,1307.67 2501.61,1307.71 2562.48,1307.71 2580.43,1289.76 2601.45,1268.74 2601.45,1161.51 2601.94,1161.01 2601.94,1120.83 2601.46,1120.34 2562.25,1120.34
GND on Bottom "Bottom-GND" (solid, remove dead copper, pour order 128): 853.8,-555.16 853.8,-370.14 869.97,-353.97 929.97,-353.97 948.29,-372.29 948.29,-555.16 1989.23,-555.16 1989.23,-377.97 2171.95,-377.97 2171.95,-298.97 2155.96,-298.97 2146.2,-308.73 2119.1,-308.73 2092.95,-282.58 2092.95,-133.97 2743.26,-133.97 2743.26,-555.16 3738.54,-555.16 3738.54,-377.87 3803.95,-377.87 3803.95,2070.99 3803.94,2070.98 -360.03,2070.98 -360.02,2070.97 -360.02,-133.97 -169.05,-133.97 -168.55,-134.47 -168.55,-283.07 -191.19,-305.72 -225.3,-305.72 -231.05,-299.97 -247.05,-299.97 -247.05,-377.97 -70.05,-377.97 -70.05,-555.16 691.31,-555.16
3V3_OUT on Bottom "NONET_L-01_P-001" (solid, pour order 96): 578.6,-253.9 570,-262.51 557.07,-262.51 537,-242.44 537,-160.24 578.6,-160.24
GND on Bottom "NONET_L08_P-001" (solid, remove dead copper, pour order 76): 2306.6,1533.79 2282.79,1533.79 2281.58,1535 2276.58,1540 2250,1540 2240,1530 2240,1482.51 2292.73,1482.51 2316.54,1506.32 2355.91,1506.32 2355.91,1545.69 2318.51,1545.69
NetC17_2 on Bottom "NONET_L08_P-001" (solid, remove dead copper, pour order 68): 2311.84,490.25 2303.8,498.29 2303.8,543.7 2311.84,551.75 2311.84,655.93 2272.47,655.93 2262.46,645.91 2262.46,459.54 2278.81,443.19 2310.74,443.19 2319.97,452.43 2319.97,481.94 2311.84,490.08
GND on Bottom "NONET_L08_P-001" (solid, remove dead copper, pour order 74): 2335.18,588.89 2335.18,539.37 2319.26,523.45 2319.26,499.83 2392.83,499.83 2399.69,506.69 2399.69,567.06 2377.86,588.89
5V0_IN on Bottom "NONET_L08_P-001" (solid, remove dead copper, pour order 20): 3329.87,-388.92 3334.82,-383.97 3355.62,-383.97 3359.97,-388.2 3359.97,-462.55 3358.39,-464.14 3358.39,-578.09 3336.73,-578.09 3336.73,-461.95 3338.1,-460.58 3338.04,-460.51 3338.04,-422.04 3329.87,-413.87
5V0_IN on Bottom "NONET_L08_P-001" (solid, remove dead copper, pour order 66): 3683.19,-456.57 3689.97,-449.79 3689.97,-374.55 3697.64,-366.89 3706.01,-366.89 3713.03,-373.9 3713.03,-455.95 3704.84,-464.14 3704.84,-578.09 3683.19,-578.09
3V3_ETH on Bottom "NONET_L08_P-001" (solid, remove dead copper, pour order 72): 2335.46,649.6 2315.75,669.31 2315.75,681.84 2321.92,688.01 2382.57,688.01 2391.59,679 2391.59,635.28 2374.83,618.53 2335.46,618.53
NetC12_1 on Bottom "NONET_L08_P-001" (solid, remove dead copper, pour order 75): 2270.29,1474.64 2270.29,1425.39 2279.34,1416.34 2400.79,1416.34 2417.82,1433.36 2417.82,1482.22 2347.71,1482.22 2347.23,1482.7 2306.97,1482.7 2298.91,1474.64
SHLD_GND on Bottom "NONET_L08_P-001" (solid, remove dead copper, pour order 10): 3604,-188 3778,-188 3778,1725 3766.97,1736.03 3489.97,1736.03 3475.97,1722.03 3475.97,78.17 3524.01,30.12 3524.01,-108.01
3V3_OUT on Bottom "NONET_L-01_P-001" (solid, pour order 95): 385.13,-158 373.31,-158 373.19,-157.87 366.61,-164.45 366.61,-176.51 365.38,-177.74 365.38,-222.32 378.86,-222.32 396.81,-204.37 396.81,-157.87 385.25,-157.87
GND on Bottom "NONET_L-01_P-001" (solid, pour order 115): 159.02,-271.19 159.02,-236.95 177.11,-218.86 188.86,-218.86 190,-220 190,-250 168.81,-271.19 162.96,-271.19
3V3_OUT on Bottom "NONET_L08_P-001" (solid, remove dead copper, pour order 93): 349.25,-346.87 349.25,-309.69 301.77,-309.69 293.41,-318.05 293.41,-340.68 299.59,-346.87
3V3_OUT on Bottom "NONET_L-01_P-001" (solid, remove dead copper, pour order 91): 65.81,-249.37 68.04,-251.6 68.04,-263.04 75,-270 93,-270 93,-239.24 71.63,-217.87 42.19,-217.87 42.19,-249.37
3V3_OUT on Bottom "NONET_L08_P-001" (solid, remove dead copper, pour order 89): 131.46,-347.75 131.46,-310.56 100.04,-310.56 91.68,-318.93 91.68,-341.56 97.86,-347.75
3V3_ETH on Bottom "NONET_L08_P-001" (solid, remove dead copper, pour order 84): 2380.41,1545.21 2434.79,1545.21 2450,1530 2450,1500 2440,1490 2431.69,1490 2417.82,1503.87 2417.82,1505.84 2380.41,1505.84
5V0_IN on Bottom "NONET_L08_P-001" (solid, remove dead copper, pour order 16): 1598.88,-411.18 1607.94,-402.12 1615.06,-402.12 1634.65,-421.71 1634.65,-455.37 1620.53,-469.49 1620.53,-583.44 1598.88,-583.44 1598.88,-470.57
5V0_IN on Bottom "NONET_L08_P-001" (solid, remove dead copper, pour order 19): 1819.35,-404.6 1826.91,-397.04 1851.41,-397.04 1858.42,-404.05 1858.42,-412.49 1858.42,-440.18 1841.01,-457.59 1841.01,-583.44 1819.35,-583.44
5V0_IN on Bottom "NONET_L08_P-001" (solid, remove dead copper, pour order 14): 1400.06,-461.13 1409.97,-451.22 1409.97,-403.97 1399.97,-393.97 1379.32,-393.97 1369.32,-403.97 1369.32,-455.92 1378.41,-465.01 1378.41,-583.44 1400.06,-583.44
5V0_IN on Bottom "NONET_L08_P-001" (solid, remove dead copper, pour order 12): 715.85,-460.78 715.85,-406.61 711.84,-402.59 682.71,-402.59 676.28,-409.02 676.28,-461.36 685.49,-470.57 685.49,-583.44 707.15,-583.44 707.15,-469.49
GND on PWR "PWR-GND" (solid, remove dead copper, pour order 136): 853.8,-555.16 853.8,-370.14 869.97,-353.97 929.97,-353.97 948.29,-372.29 948.29,-555.16 1989.23,-555.16 1989.23,-377.97 2171.95,-377.97 2171.95,-298.97 2155.96,-298.97 2146.2,-308.73 2119.1,-308.73 2092.95,-282.58 2092.95,-133.97 2743.26,-133.97 2743.26,-555.16 3738.54,-555.16 3738.54,-377.87 3803.95,-377.87 3803.95,2070.99 3803.94,2070.98 -360.03,2070.98 -360.02,2070.97 -360.02,-133.97 -169.05,-133.97 -168.55,-134.47 -168.55,-283.07 -191.19,-305.72 -225.3,-305.72 -231.05,-299.97 -247.05,-299.97 -247.05,-377.97 -70.05,-377.97 -70.05,-555.16 691.31,-555.16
